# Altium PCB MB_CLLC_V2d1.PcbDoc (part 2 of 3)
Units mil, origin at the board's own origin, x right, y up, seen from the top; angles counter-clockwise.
Board outline 9000 x 7000 mil, 2 copper layers (Top Layer, Bottom Layer); 436 components, 223 nets, 1335 pads, 200 vias.
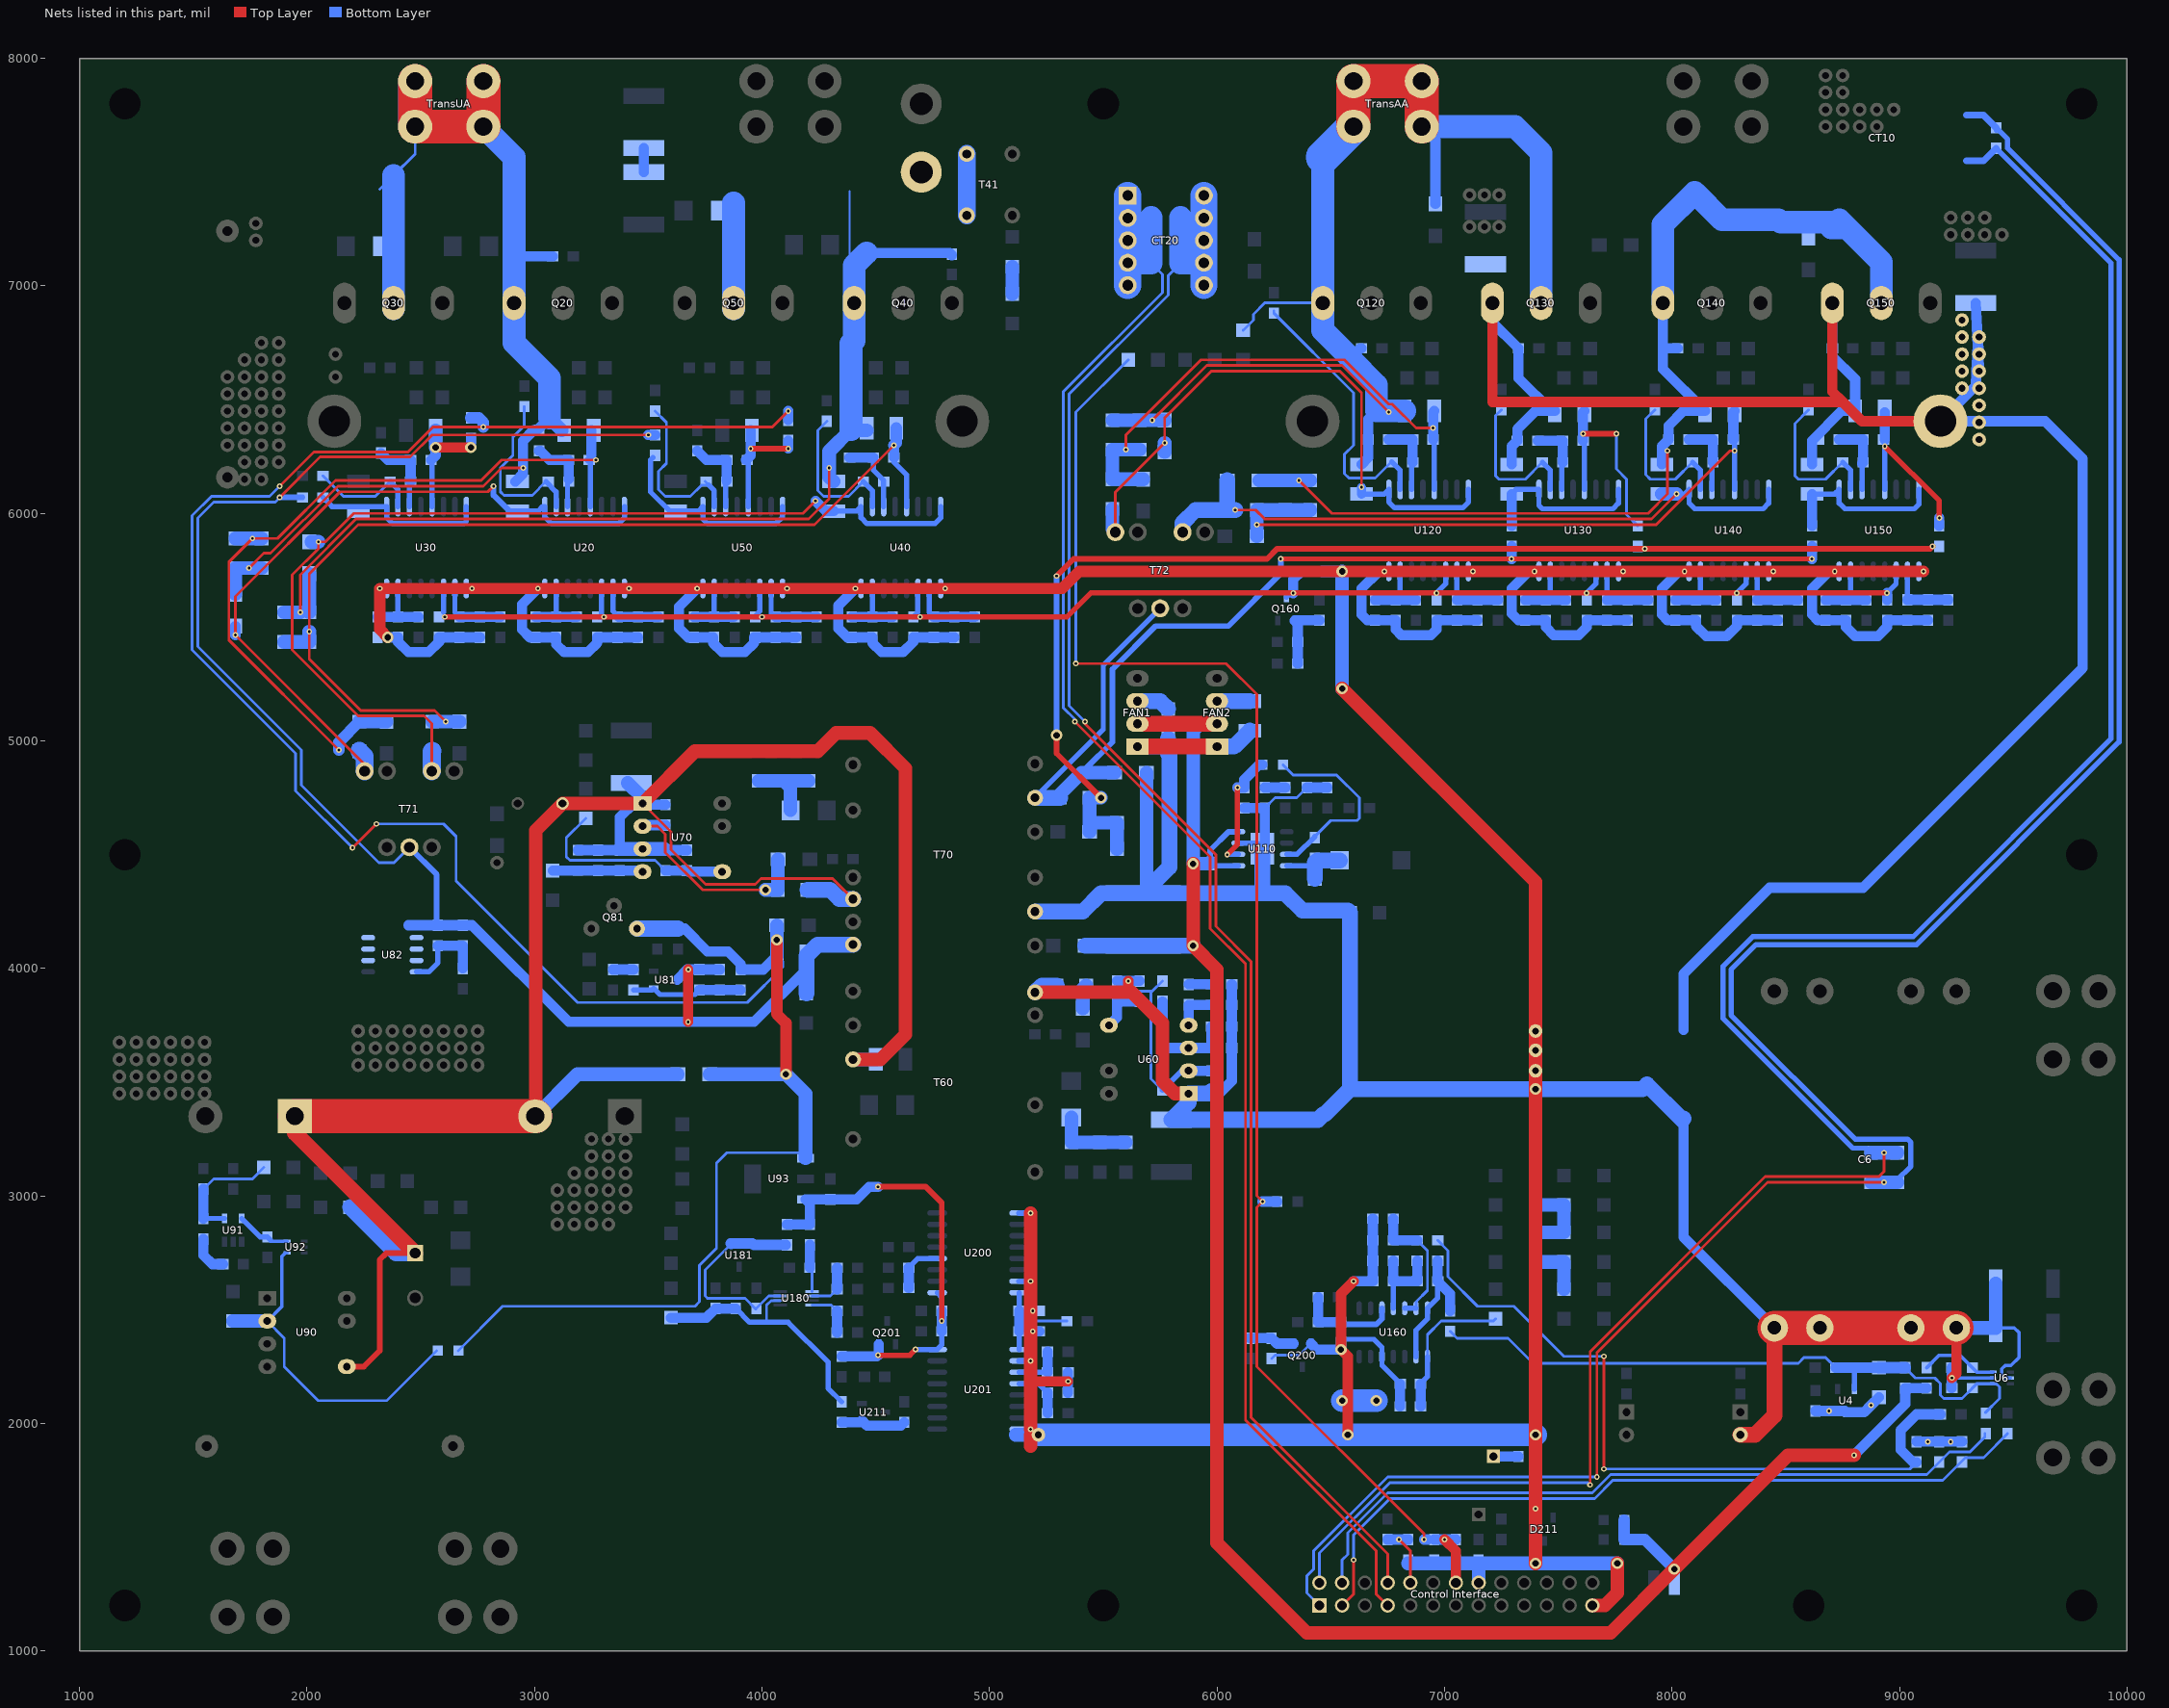
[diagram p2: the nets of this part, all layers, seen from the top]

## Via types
v1: diameter 25, hole 12, Top Layer to Bottom Layer, 169 vias
v2: diameter 50, hole 28, Top Layer to Bottom Layer, 31 vias

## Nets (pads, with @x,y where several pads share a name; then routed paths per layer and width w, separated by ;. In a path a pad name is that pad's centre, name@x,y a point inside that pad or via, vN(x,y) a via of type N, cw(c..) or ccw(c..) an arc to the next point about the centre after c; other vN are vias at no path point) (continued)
+3.3VBU: C93.2 C203.2 C206.2 Q201.2 R189.2 R190.1 R211.1 U93.3 U200.1 U201.16 | length 2135.8
  Top Layer w23: v1(4510,2300) 4650,2300 v1(4675,2325)
  Top Layer w25: v1(4510,3040) 4720,3040 4790,2970 v1(4790,2450)
  Bottom Layer w23: v1(4675,2325) U201.16@4770,2325 4790,2345 C206.2@4790,2405 ; U200.1@4770,2575 4790,2555 C203.2@4790,2495
  Bottom Layer w45: R190.1@4110,2875 R189.2@4210,2875 4210,2965.59 U93.3@4191.14,2984.45 4244.45,2984.45 4245,2985 C93.2@4300,2985 4415,2985 4470,3040 v1(4510,3040) ; R211.1@4350,2295 4505,2295 v1(4510,2300) 4512.6,2302.6 Q201.2@4512.6,2347.64 ; C206.2@4790,2405 v1(4790,2450) C203.2@4790,2495
+6V: C5.2 C8.2 R4.2 R5.1 R160.1 R240.1 U4.2 U6.1 | length 2859
  Bottom Layer w12: R160.1@7025,2405 7055,2375 7280,2375 7390,2265 8555,2265 8580,2290 8675,2290 R5.1@8720,2245 ; R4.2@9025,2245 9070,2200 9155,2200 9180,2175 9180,2125 9195,2110 9275,2110 C8.2@9320,2155 ; R240.1@9377.5,2047.5 9440,2110 9440,2160 9426,2174 U6.1@9412.5,2174
  Bottom Layer w15: C8.2@9320,2155 9339,2174 U6.1@9412.5,2174
  Bottom Layer w23: U4.2@8802.4,2151.18 8802.4,2227.4 8820,2245
  Bottom Layer w45: R5.1@8720,2245 8820,2245 C5.2@8910,2245
  Bottom Layer w50: C5.2@8910,2245 R4.2@9025,2245
+12V: C76.1 C110.2 D75.2 D191.2 D192.2 FAN1.2 FAN2.2 L190.2 R4.1 R232.1 U110.1 U110.4 | length 9115.2
  Top Layer w60: v2(5895,4460) v2(5895,4100) 6000,3995 6000,1475 6395,1080 7730,1080 v2(8010,1360) 8510,1860 v1(8800,1860)
  Top Layer w70: FAN1.2@5650,5075 FAN2.2@6000,5075
  Bottom Layer w25: C110.2@5963,4460 5954,4451 U110.1@6093.7,4451 ; C110.2@5970,4467 5970,4520 6051,4601 U110.4@6093.7,4601
  Bottom Layer w45: v1(8800,1860) 9025,2085 R4.1@9025,2155 R232.1@9120,2155
  Bottom Layer w50: D191.2@7790,1575 D192.2@7790,1490 7880,1490 v2(8010,1360)
  Bottom Layer w60: C110.2@5970,4467 5963,4460 v2(5895,4460) 5895,5045 5925,5075 FAN2.2@6000,5075
  Bottom Layer w70: D75.2@5420,4100 C76.1@5675,4100 ; C76.1@5685,4100 v2(5895,4100)
+15V_BA: C77.2 D76.2 R76.2 R77.2 R137.1 R157.1 | length 5389.6
  Top Layer w25: v2(5295,5025) 5295,4945 v2(5490,4750) ; v1(5295,5725) 5370,5800 6220,5800 6265,5845 v1(7880,5845) 9135,5845 v1(9145,5855)
  Bottom Layer w25: v2(5295,5025) v1(5295,5725)
  Bottom Layer w60: D76.2@5440,4600 5440,4640 ; v2(5490,4750) C77.2@5440,4750 5440,4640 ; R77.2@5555,4640 5440,4640 ; R76.2@5560,4525 R77.2@5560,4640
+15V_BA_A: C80.2 C120.1 C122.1 D80.2 R80.2 R81.2 U120.5 | length 2410.1
  Top Layer w12: v1(5600,6280) 5600,6345 5930,6675 6560,6675 6755,6480 6770,6480 6875,6375 v1(6950,6375)
  Bottom Layer w23: C122.1@6950,6325 6955,6320 U120.5@6955,6105
  Bottom Layer w45: C122.1@6950,6325 v1(6950,6375) 6950,6445 C120.1@6955,6450
  Bottom Layer w60: R81.2@5660,6280 v1(5600,6280) R80.2@5540,6280 C80.2@5540,6150 D80.2@5675,6150
+15V_BA_B: C79.2 C140.1 C142.1 D78.2 R78.2 R79.2 U140.5 | length 2933.8
  Top Layer w12: v1(6175,5950) 7930,5950 8255,6275 v1(8275,6275)
  Bottom Layer w23: C142.1@8270,6325 8275,6320 v1(8275,6275) U140.5@8275,6105
  Bottom Layer w45: C142.1@8270,6325 8270,6445 C140.1@8275,6450
  Bottom Layer w60: D78.2@6175,5900 v1(6175,5950) C79.2@6175,6015 R79.2@6300,6015 R78.2@6410,6015
+20V: C86.2 D71.1 D86.2 D91.1 Q81.1 R37.1 R57.1 R82.2 R83.2 R86.1 U93.1 | length 11604.2
  Top Layer w12: v1(1880,6120) 2030,6270 2443.89,6270 2553.89,6380 v1(2775,6380) 4045,6380 v1(4115,6450) ; v1(2200,4530) v1(2305,4635)
  Top Layer w50: v2(4065,4125) 4065,3800 4105,3760 v2(4105,3535)
  Bottom Layer w12: v1(1880,6120) 1835,6075 1580,6075 1495,5990 1495,5400 1950,4945 1950,4780 v1(2200,4530) ; v1(2305,4635) 2600,4635 2655,4580 2655,4385 3190,3850 3935,3850 4090.11,4005.11 4090.11,4029.89 C86.2@4065,4055 ; D91.1@2665,2320 2860,2515 3705,2515 3725,2535 3725,2695 3800,2770 3800,3145 3845,3190 4166.69,3190 U93.1@4191.14,3165.55
  Bottom Layer w45: R83.2@3630,4175 3660,4175 3760,4075 3850,4075 3905,4020 R86.1@3905,3995 4005,3995 C86.2@4065,4055 ; R57.1@4115,6410 v1(4115,6450)
  Bottom Layer w50: R37.1@2720,6420 2755,6420 2775,6400 v1(2775,6380)
  Bottom Layer w60: D71.1@3770,3535 v2(4105,3535) 4191.14,3448.86 U93.1@4191.14,3165.55 ; C86.2@4065,4055 v2(4065,4125) D86.2@4065,4190
  Bottom Layer w70: Q81.1@3450,4175 R82.2@3540,4175 R83.2@3630,4175
+20V_BU_A: C20.1 C22.1 C102.2 D102.2 R102.2 R103.2 U20.5 | length 3547.5
  Top Layer w12: v1(2140,4960) 1656.5,5443.5 1656.5,5786.5 v1(1760,5890) 1870,5890 2125,6145 2765,6145 2855,6235 v1(3270,6235)
  Bottom Layer w23: C22.1@3230,6235 C22.1@3235,6230 ; C22.1@3240,6235 3245,6230 U20.5@3245,6030
  Bottom Layer w45: C22.1@3250,6255 C20.1@3250,6365
  Bottom Layer w50: v1(2140,4960) 2140,4995 C102.2@2230,5085
  Bottom Layer w60: R102.2@1685,5890 v1(1760,5890) R103.2@1800,5890 ; C102.2@2230,5085 D102.2@2350,5085
+20V_BU_B: C40.1 C42.1 C100.2 D100.2 R100.2 R101.2 U40.5 | length 4519.9
  Top Layer w12: v1(2610,5085) 2561,5134 2236,5134 2010,5360 v1(2010,5480) 2010,5735 2225,5950 4230,5950 v1(4580,6300)
  Bottom Layer w23: C42.1@4580,6225 4635,6170 U40.5@4635,6030
  Bottom Layer w45: C42.1@4580,6245 v1(4580,6300)
  Bottom Layer w50: v1(4580,6300) 4590,6310 C40.1@4590,6375
  Bottom Layer w60: R101.2@1900,5435 R100.2@2010,5435 v1(2010,5480) ; C100.2@2550,5085 v1(2610,5085) D100.2@2670,5085
-5V_BA: C77.1 D77.1 R138.2 R158.2 T70.13 T72.3 | length 5386.3
  Top Layer w23: v1(6280,5800) v1(7295,5800) v1(8615,5800)
  Bottom Layer w23: T70.13@5200,4750 5500,5050 5500,5332.48 T72.3@5750,5582.48
  Bottom Layer w25: 5425,4865 5425,4880 5540,4995 5540,5315 5730,5505 6050,5505 6280,5735 v1(6280,5800)
  Bottom Layer w45: v1(7295,5800) R138.2@7295,5855 ; v1(8615,5800) R158.2@8615,5855
  Bottom Layer w60: C77.1@5310,4750 5310,4765 5405,4860 D77.1@5550,4860
  Bottom Layer w70: T70.13@5200,4750 C77.1@5310,4750
-5V_BA_A: C80.1 C123.1 D81.1 T72.10 U120.1 U120.8 | length 2783.5
  Top Layer w12: T72.10@5553.15,5917.52 5553.15,6093.15 v1(5770,6310) 5770,6420 5975,6625 6540,6625 6635,6530 v1(6635,6115)
  Bottom Layer w23: C123.1@6635,6085 6735,6085 U120.1@6755,6105 6755,6050 6780,6025 7080,6025 7105,6050 U120.8@7105,6105
  Bottom Layer w40: C123.1@6635,6085 v1(6635,6115)
  Bottom Layer w60: C80.1@5540,6020 5540,5930.67 T72.10@5553.15,5917.52 ; D81.1@5770,6270 v1(5770,6310)
-5V_BA_B: C79.1 C143.1 D79.1 T72.7 U140.1 U140.8 | length 3047
  Top Layer w12: v1(6080,6015) 6170,6015 6210,5975 7910,5975 v1(8020,6085)
  Bottom Layer w23: v1(8020,6085) 8055,6085 U140.1@8075,6105 8075,6045 8100,6020 8400,6020 8425,6045 U140.8@8425,6105
  Bottom Layer w60: C143.1@7955,6085 v1(8020,6085)
  Bottom Layer w70: T72.7@5848.43,5917.52 5848.43,5958.43 5905,6015 C79.1@6045,6015 ; D79.1@6045,6145 C79.1@6045,6015 ; v1(6080,6015) C79.1@6045,6015
-5V_BU_A: C23.1 C102.1 D103.1 T71.10 U20.1 U20.8 | length 3235.8
  Top Layer w12: T71.10@2253.15,4867.52 2253.15,4896.85 v1(1685,5465) 1685,5635 2145,6095 2795,6095 v1(2820,6120)
  Bottom Layer w23: C23.1@2915,6010 C23.1@2925,6010 3015,6010 U20.1@3035,6030 ; U20.1@3045,6030 3045,5985 3075,5955 3370,5955 3395,5980 U20.8@3395,6030
  Bottom Layer w25: v1(2820,6120) 2820,6080 2890,6010 C23.1@2915,6010
  Bottom Layer w45: v1(1685,5465) D103.1@1685,5505
  Bottom Layer w80: C102.1@2230,4955 2253.15,4931.85 T71.10@2253.15,4867.52
-5V_BU_B: C43.1 C100.1 D101.1 T71.7 U40.1 U40.8 | length 4567.6
  Top Layer w12: T71.7@2548.43,4867.52 2548.43,5076.57 2515,5110 2225,5110 1935,5400 1935,5730 2050,5845 v1(2050,5875) 2080,5875 2205,6000 4180,6000 v1(4235,6055)
  Bottom Layer w0: D101.1@2010,5875 2015,5880 D101.1@2020,5875
  Bottom Layer w23: C43.1@4315,6010 4415,6010 U40.1@4435,6030 4435,5981.69 4461.69,5955 4760,5955 4785,5980 U40.8@4785,6030
  Bottom Layer w45: v1(4235,6055) 4280,6010 C43.1@4315,6010
  Bottom Layer w60: D101.1@2020,5875 v1(2050,5875)
  Bottom Layer w80: T71.7@2548.43,4867.52 2548.43,4953.43 C100.1@2550,4955
-5VBU: C86.1 C87.1 C88.1 R38.2 R58.2 R68.2 R87.2 R89.2 T70.8 T71.3 U81.3 U82.2 | length 7510.3
  Top Layer w12: v1(1880,6070) 2058,6248 2453,6248 2550,6345 v1(3500,6345)
  Top Layer w45: v1(3675,3765) 3675.59,3765.59 v1(3675.59,3995)
  Bottom Layer w12: v1(1880,6070) 1860,6050 1590,6050 1520,5980 1520,5415 1975,4960 1975,4805 2315,4465 2382.52,4465 T71.3@2450,4532.48
  Bottom Layer w25: v1(1880,6070) R38.2@1980,6070 ; T71.3@2450,4532.48 2570,4412.48 C88.1@2570,4190
  Bottom Layer w45: 2445,4190 2570,4190 C88.1@2575,4190 R89.2@2685,4190 2725,4190 3150,3765 v1(3675,3765) 3965,3765 4195,3995 ; v1(3500,6345) R58.2@3530,6345 ; U81.3@3626.18,3950 3671.18,3995 v1(3675.59,3995) R87.2@3725,3995 R68.2@3815,3995
  Bottom Layer w70: C87.1@4195,3890 4195,3995 C86.1@4195,4055 4245,4105 T70.8@4400,4105
C_BA_A: C120.2 C123.2 D81.2 D130.2 Q120.3 Q130.2 R12.2 R80.1 R81.1 R123.1 R124.1 TransAA.1 | length 6023.5
  Top Layer w12: v1(5715,6410) 5955,6650 6550,6650 v1(6755,6445)
  Top Layer w150: TransAA.1@6600,7700 TransAA.1@6600,7900 TransAA.1@6900,7900 TransAA.1@6900,7700
  Bottom Layer w12: R12.2@6115,6805 6160,6850 6160,6875 6210,6925 Q120.3@6465,6925
  Bottom Layer w45: 6585,6680 6587.5,6682.5 6630,6725 R123.1@6635,6725 ; C123.2@6635,6215 6665,6245 R124.1@6665,6325 6665,6415 6700,6450 ; TransAA.1@6900,7700 6960,7640 D130.2@6960,7360
  Bottom Layer w60: R80.1@5540,6410 R81.1@5660,6410 v1(5715,6410) D81.2@5770,6410
  Bottom Layer w100: 6465,7565 Q120.3@6465,6925 6465,6805 6587.5,6682.5 ; 6585,6680 6700,6565 6700,6450 C120.2@6825,6450 ; TransAA.1@6900,7700 7310,7700 7425,7585 Q130.2@7425,6925
  Bottom Layer w150: 6465,7565 TransAA.1@6600,7700
C_BA_B: C140.2 C143.2 CT10.6 CT10.12 D79.2 D150.2 Q140.3 Q150.2 R78.1 R79.1 R143.1 R144.1 | length 4914.6
  Top Layer w12: v1(6360,6145) 6505,6000 7895,6000 7980,6085 v1(7980,6275)
  Bottom Layer w45: C143.2@7955,6215 7955,6295 R144.1@7985,6325 7985,6385 8050,6450 C140.2@8145,6450 7960,6635 7960,6725 ; Q140.3@7960,6925 7960,6725 ; R143.1@8025,6725 7960,6725
  Bottom Layer w60: D79.2@6185,6145 R79.1@6300,6145 v1(6360,6145) R78.1@6410,6145
  Bottom Layer w100: Q140.3@7960,6925 7960,7270 8100,7410 8220,7290 8467.65,7290 8477.65,7280 8725,7280 ; Q150.2@8920,6925 8920,7105 8735,7290 8725,7280 ; 8725,7280 8700,7255 8750,7255 8725,7280
C_BU_A: C20.2 C23.2 D30.2 D103.2 Q20.3 Q30.2 R23.1 R24.1 R102.1 R103.1 TransUA.1 | length 5440.3
  Top Layer w12: v1(1745,5760) 1810,5825 1840,5825 2135,6120 2775,6120 2855,6200 v1(2950,6200)
  Top Layer w150: TransUA.1@2475,7900 TransUA.1@2475,7700 TransUA.1@2775,7700 TransUA.1@2775,7900
  Bottom Layer w12: 2320,7425 2380,7485 2475,7580 TransUA.1@2475,7700
  Bottom Layer w45: 2910,7130 R23.1@3080,7130 ; C23.2@2915,6140 2950,6175 v1(2950,6200) 2950,6320 2995,6365 3010,6365 3065,6420
  Bottom Layer w60: D103.2@1685,5645 R102.1@1685,5760 v1(1745,5760) R103.1@1800,5760 ; 3065,6420 C20.2@3120,6365
  Bottom Layer w100: Q30.2@2380,6900 Q30.2@2380,6925 2380,7485 ; TransUA.1@2775,7700 2910,7565 2910,7130 Q20.3@2910,6925 2910,6750 3065,6595 3065,6420
  Bottom Layer w150: TransUA.1@2475,7700 TransUA.1@2475,7900
C_BU_B: C40.2 C43.2 D50.2 D101.2 pad.61 Q40.3 Q50.2 R43.1 R44.1 R100.1 R101.1 T41.2 | length 5785.2
  Top Layer w12: v1(1970,5565) 1970,5730 2215,5975 4205,5975 4295,6065 v1(4295,6200)
  Bottom Layer w10: Q40.3@4385,6900 4385,7415
  Bottom Layer w45: 4460,7145 4825,7145 R43.1@4835,7135
  Bottom Layer w60: R101.1@1900,5565 v1(1970,5565) ; R100.1@2010,5565 D101.2@2010,5735 ; C43.2@4315,6140 4295,6160 v1(4295,6200) R44.1@4295,6245 4295,6273 4391,6369 4395,6365 C40.2@4460,6365
  Bottom Layer w80: T41.2@4900,7310 T41.2@4900,7580
  Bottom Layer w100: Q50.2@3875,6900 Q50.2@3875,6925 3875,7365 ; 4391,6369 4391,6746 4405,6760 Q40.3@4405,6925 4405,7090 4460,7145
GND: "Control Interface.16" "Control Interface.25" C5.1 C6.2 C7.1 C8.1 C24.1 C25.1 C26.2 C27.1 C34.1 C35.1 C36.2 C37.1 C44.1 C45.1 C46.2 C47.1 C54.1 C55.1 C56.2 C57.1 C61.1 C62.1 C63.1 C64.1 C66.1 C68.1 C76.2 C110.1 C111.1 C112.1 C114.1 C115.1 C116.1 C124.1 C125.1 C126.2 C127.1 C128.1 C130.2 C133.2 C134.1 C135.1 C136.2 C137.1 C144.1 C145.1 C146.2 C147.1 C148.1 C150.2 C153.2 C154.1 C155.1 C156.2 C157.1 C161.1 C162.1 C164.1 C169.1 C170.1 C194.1 C201.1 C202.1 C204.1 C208.1 C209.1 C212.1 C217.1 C239.1 C240.1 D77.2 D111.1 D211.1 FAN1.1 FAN2.1 HS2.1 pad.8@5215,1950 pad.50 pad.51 pad.52 pad.53 pad.54 pad.55 pad.56@8450,2420 pad.56@9250,2420 pad.57 pad.58 pad.59 Power.2 Q130.3 Q150.3 Q200.2 R6.2 R27.2 R39.2 R47.2 R59.2 R62.2 R64.2 R66.2 R76.1 R77.1 R111.2 R112.2 R127.2 R133.1 R134.1 R139.2 R147.2 R153.1 R154.1 R159.2 R162.2 R164.2 R167.2 R168.2 R194.2 R217.2 R230.2 R231.2 T60.8 T70.10 U4.3 U6.2 U6.5 U20.9 U20.16 U30.9 U30.16 U40.9 U40.16 U50.9 U50.16 U60.1 U110.3 U110.9 U120.9 U120.16 U130.9 U130.16 U140.9 U140.16 U150.9 U150.16 U160.12 U200.9 U200.15 U201.2 U201.8 | length 48783.6
  Top Layer w45: 5180,2185 v1(5345,2185) ; v1(5610,3945) 5610,3910 5625,3895 ; v2(6575,1950) 6575,2295 v2(6545,2325) 6545,2570 v1(6600,2625) ; Q130.3@7210,6925 7210,6490 8750,6490 ; Q150.3@8705,6925 8705,6535 8750,6490 ; HS2.1@9180,6405 8835,6405 8750,6490 ; v1(9230,2200) 9250,2220 pad.56@9250,2420
  Top Layer w50: v2(2355,5455) 2320,5490 v1(2320,5670) v1(2725,5670) v1(3015,5670) v1(3415,5670) v1(3715,5670) v1(4110,5670) v1(4410,5670) v1(4805,5670) 5320,5670 5395,5745 v2(6550,5745) v1(6735,5745) v1(7125,5745) v1(7395,5745) v1(7785,5745) v1(8055,5745) v1(8445,5745) v1(8715,5745) v1(9105,5745)
  Top Layer w60: 5180,1900 5180,1950 ; v1(5180,1975) 5180,2185 v1(5180,2275) v1(5180,2625) v1(5180,2925) ; T60.8@5200,3895 5625,3895 5760,3760 5760,3505 5815,3450 U60.1@5875,3450 ; v2(6550,5230) 7400,4380 pad.59@7400,3725 pad.58@7400,3640 pad.57@7400,3550 v2(7400,3470) v2(7400,1950) v1(7400,1625) v2(7400,1385) ; 7650,1200 7705,1200 7760,1255 v2(7760,1385)
  Top Layer w70: FAN1.1@5650,4975 FAN2.1@6000,4975 ; Power.2@8300,1950 8365,1950 8450,2035 pad.56@8450,2420
  Top Layer w150: pad.56@8450,2420 C6.2@8650,2420 C6.2@9050,2420 pad.56@9250,2420
  Bottom Layer w12: C112.1@6210,4705 6255,4750 6350,4750 R112.2@6395,4795 ; C204.1@6240,2285 6255,2300 6361.22,2300 Q200.2@6412.4,2351.18
  Bottom Layer w15: v1(9230,2200) U6.2@9412.5,2200 ; R231.2@9423.03,2420 9505,2420 9525,2400 9525,2290 9490,2255 9465,2255 9450,2240 9450,2210 9460,2200 U6.5@9487.5,2200
  Bottom Layer w23: v1(2320,5670) U30.16@2350,5670 ; U30.9@2700,5670 v1(2725,5670) ; v1(4410,5670) U40.16@4435,5670 ; U110.3@6093.7,4551 6175,4551 U110.9@6200,4526 ; C170.1@6545,2355 6560,2370 6690,2370 6725,2335 U160.12@6725,2293.7 6725,2255 C169.1@6805,2175
  Bottom Layer w25: U201.2@5130,2275 v1(5180,2275) ; U200.15@5130,2625 v1(5180,2625) ; U200.9@5130,2925 v1(5180,2925) ; v1(7400,1625) 7402.6,1622.4 D211.1@7402.6,1586.18
  Bottom Layer w45: v2(2355,5455) C34.1@2400,5455 2400,5435 2445,5390 2535,5390 2580,5435 C36.2@2580,5455 C37.1@2670,5455 R39.2@2760,5455 ; v1(3015,5670) 2945,5600 2945,5490 2980,5455 C25.1@3005,5455 C24.1@3095,5455 3095,5425 3130,5390 3235,5390 3275,5430 C26.2@3275,5455 ; C26.2@3285,5455 C27.1@3365,5455 R27.2@3455,5455 ; v1(3715,5670) 3635,5590 3635,5495 3675,5455 C55.1@3700,5455 3785,5455 3785,5430 3825,5390 3925,5390 3965,5430 3965,5455 C56.2@3970,5455 C57.1@4060,5455 R59.2@4150,5455 ; v1(4410,5670) 4335,5595 4335,5495 4375,5455 C45.1@4395,5455 C44.1@4485,5455 4485,5430 4525,5390 4620,5390 4665,5435 C46.2@4665,5455 C47.1@4755,5455 R47.2@4845,5455 ; v1(5190,2405) C212.1@5220,2405 ; C202.1@5345,2135 v1(5345,2185) C208.1@5345,2225 ; C62.1@5560,3945 v1(5610,3945) R62.2@5660,3945 ; C61.1@5975,3460 6020,3460 6065,3505 C66.1@6065,3650 R66.2@6065,3745 C64.1@6065,3840 R64.2@6065,3930 ; C111.1@6120,4705 C112.1@6210,4705 6210,4536 U110.9@6200,4526 ; R112.2@6395,4795 R111.2@6485,4795 ; Q200.2@6412.4,2351.18 6438.58,2325 v2(6545,2325) ; v1(6600,2625) C161.1@6685,2625 R162.2@6685,2715 C162.1@6685,2805 R164.2@6685,2900 ; v1(6735,5745) 6710,5745 6635,5670 6635,5555 6660,5530 C125.1@6695,5530 C124.1@6785,5530 6785,5490 6810,5465 6940,5465 6965,5490 C126.2@6965,5530 C127.1@7055,5530 R127.2@7145,5530 ; R168.2@6805,2075 C169.1@6805,2175 ; Q130.3@7210,6925 7210,6840 R133.1@7325,6725 7325,6595 C130.2@7470,6450 ; C133.2@7295,6215 7295,6295 R134.1@7320,6320 7320,6370 7400,6450 C130.2@7470,6450 ; v1(7395,5745) 7370,5745 7295,5670 7295,5560 7325,5530 C135.1@7355,5530 C134.1@7445,5530 7445,5500 7480,5465 7590,5465 7625,5500 C136.2@7625,5530 C137.1@7715,5530 R139.2@7805,5530 ; C130.2@7485,6450 C130.2@7470,6450 ; 8050,3340 8050,2820 pad.56@8450,2420 ; 8050,3730 8050,3975 8430,4355 8840,4355 9805,5320 9805,6240 9640,6405 HS2.1@9180,6405 9335,6560 9338.14,6620.61 9338.39,6625.6 9341.67,6688.88 9342.26,6700.4 9344.28,6739.41 ; v1(8055,5745) 8030,5745 7955,5670 7955,5555 7980,5530 C145.1@8015,5530 C144.1@8105,5530 8105,5505 8150,5460 8240,5460 8285,5505 C146.2@8285,5530 C147.1@8375,5530 R147.2@8465,5530 ; C153.2@8615,6215 8615,6320 8745,6450 C150.2@8805,6450 8805,6590 8705,6690 R153.1@8705,6725 Q150.3@8705,6925 ; R6.2@8630,2055 v1(8690,2055) 8758.82,2055 U4.3@8765,2048.82 8843.82,2048.82 v1(8875,2080) C5.1@8910,2115 ; C6.2@8649.72,2412.52 C6.2@8650.09,2412.5 ; v1(8715,5745) 8690,5745 8615,5670 8615,5555 8640,5530 C155.1@8675,5530 C154.1@8765,5530 8765,5500 8805,5460 8905,5460 8945,5500 C156.2@8945,5530 C157.1@9035,5530 R159.2@9125,5530 ; C164.1@9075,1920 v1(9125,1920) C240.1@9175,1920 v1(9225,1920) C239.1@9275,1920 ; C8.1@9230,2155 v1(9230,2200) C7.1@9230,2245 ; C148.1@9335,6925 9342.52,6774.63 9344.28,6739.41 ; 9344.28,6739.41 9345.55,6763.94 9346.13,6775.2 9346.14,6774.9 9348.07,6699.95 pad.51@9350,6625 9346.26,6699.81 9344.28,6739.41
  Bottom Layer w50: R167.2@6460,5745 v2(6550,5745)
  Bottom Layer w60: 5115,1950 pad.8@5215,1950 ; C76.2@5690,4345 R76.1@5690,4525 R77.1@5690,4640 D77.2@5690,4860 ; v2(6550,5230) v2(6550,5745) ; C209.1@6840,1385 v2(7400,1385) v2(7760,1385) ; 7150,1300 R217.2@7150,1375 ; pad.56@9250,2420 R231.2@9423.03,2420 R230.2@9423.03,2615
  Bottom Layer w70: T60.8@5200,3895 5230,3925 C63.1@5295,3925 ; T70.10@5200,4250 5410,4250 5490,4330 C76.2@5675,4330 ; FAN1.1@5650,4975 5755,4975 ; C115.1@5785,5010 5785,4945 5790,4940 5790,4445 5690,4345 C76.2@5675,4330 ; C61.1@5975,3460 5965,3450 U60.1@5875,3450 5875,3410 C68.1@5800,3335 6443.93,3335 6468.93,3360 6475,3360 6585,3470 ; FAN2.1@6000,4975 6075,4975 C116.1@6145,5045 ; U110.9@6200,4526 6200,4330 ; 8050,3340 8045,3335 7890,3490 7870,3470 v2(7400,3470) 6585,3470 ; C76.2@5675,4330 C110.1@5970,4330 6200,4330 ; 6200,4330 6300,4330 6375,4255 D111.1@6430,4255 6575,4255 C114.1@6585,4245 6585,3470
  Bottom Layer w100: pad.8@5215,1950 v2(6575,1950) v2(7400,1950) ; v2(6550,2100) v2(6700,2100)
  other v1: 5190,2495
Half-BUS: C2.2 C3.1 C67.1 C70.1 C72.1 C73.1 C74.1 C98.1 C99.1 D70.1 D71.2 L90.1 R70.2 R72.2 R94.2 T60.11 T70.6 U70.1 U70.3 U90.5 | length 10711.8
  Top Layer w12: U70.1@3475,4725 3600,4600 3600,4522 3752,4370 3970,4370 3995,4395 4310,4395 T70.6@4400,4305
  Top Layer w25: U90.5@2175,2250 2250,2250 2320,2320 2320,2720 2348.43,2748.43 L90.1@2475,2748.43
  Top Layer w50: C2.2@3003.15,3350 C2.2@3005,3351.85
  Top Layer w60: C2.2@3005,3351.85 3005,4606.57 C98.1@3123.43,4725 U70.1@3475,4725 3705,4955 4245,4955 4325,5035 4475,5035 4630,4880 4630,3710 4520,3600 T60.11@4400,3600
  Top Layer w70: C3.1@1946.85,3350 1946.85,3276.57 L90.1@2475,2748.43
  Top Layer w150: C3.1@1946.85,3350 C2.2@3003.15,3350
  Bottom Layer w45: D70.1@3190,4520 R70.2@3280,4520 C72.1@3375,4520 C72.1@3380,4520 ; C72.1@3375,4525 3375,4665 3435,4725 U70.1@3475,4725 3480,4720 C70.1@3575,4720 ; R72.2@3570,4525 R72.2@3575,4520 C73.1@3670,4520
  Bottom Layer w60: C2.2@3003.15,3350 3188.15,3535 D71.2@3630,3535 ; C72.1@3375,4525 U70.3@3475,4525 R72.2@3570,4525 ; C99.1@3410,4815 3475,4750 U70.1@3475,4725 ; T60.11@4400,3600 C67.1@4500,3600
  Bottom Layer w70: R94.2@2190,2950 2391.57,2748.43 L90.1@2475,2748.43 ; C74.1@4200,4345 4300,4345 4340,4305 T70.6@4400,4305
NetC7_2: C7.2 R232.2 U6.3 | length 345.9
  Bottom Layer w15: R232.2@9120,2245 9175,2300 9265,2300 C7.2@9320,2245 9339,2226 U6.3@9412.5,2226
NetC11_1: "Control Interface.2" C11.1 CT10.4 R10.1 R11.1 | length 10056.4
  Top Layer w12: v1(7640,1730) 7640,2315 8410,3085 8910,3085 8932.5,3107.5 v1(8932.5,3190)
  Bottom Layer w12: 6450,1300 6450,1430 6760,1740 7630,1740 v1(7640,1730)
  Bottom Layer w23: R10.1@8875,3190 8855,3210 8795,3210 8225,3780 8225,4010 8355,4140 9060,4140 9930,5010 9930,7100 C11.1@9425,7605
  Bottom Layer w30: CT10.4@9295,7550 9370,7550 C11.1@9425,7605
  Bottom Layer w60: R10.1@8875,3190 v1(8932.5,3190) R11.1@8990,3190
NetC11_2: "Control Interface.1" C11.2 CT10.2 R10.2 R11.2 | length 10530.6
  Top Layer w12: v1(7670,1765) 7670,2310.3 8419.69,3060 v1(8932.5,3060)
  Bottom Layer w12: 6450,1200 6395,1255 6395,1330 6425,1360 6425,1440 6750,1765 v1(7670,1765)
  Bottom Layer w23: R10.2@8875,3060 R10.2@8875,3075 ; R11.2@8990,3060 8990,3070 9050,3130 9050,3235 9035,3250 8805,3250 8260,3795 8260,3995 8370,4105 9075,4105 9965,4995 9965,7115 9475,7605 9475,7645 C11.2@9425,7695 C11.2@9425,7685
  Bottom Layer w30: CT10.2@9295,7750 9370,7750 C11.2@9425,7695
  Bottom Layer w60: R10.2@8875,3060 v1(8932.5,3060) R11.2@8990,3060
NetC12_1: "Control Interface.8" C12.1 CT20.2 R15.1 R16.1 | length 7279.1
  Top Layer w12: v1(5420,5085) 5420,5075 5995,4500 5995,4185 6150,4030 6150,2026.11 6750,1426.11 6750,1300
  Bottom Layer w12: v1(5420,5085) 5350,5155 5350,6525 5785,6960 5785,7045 R16.1@5840,7100
  Bottom Layer w100: R15.1@5840,7300 R16.1@5840,7100 5942.52,7100 CT20.2@5942.52,7101.57
  Bottom Layer w120: CT20.2@5942.52,7003.15 CT20.2@5942.52,7100 ; CT20.2@5942.52,7101.57 CT20.2@5942.52,7200 CT20.2@5942.52,7298.43 CT20.2@5942.52,7396.85
NetC12_2: "Control Interface.7" C12.2 CT20.1 R15.2 R16.2 | length 7388
  Top Layer w12: v1(5375,5085) 5970,4490 5970,4175 6125,4020 6125,2015 6700,1440 6700,1250 6750,1200
  Bottom Layer w12: v1(5375,5085) 5375,5095 5325,5145 5325,6535 5760,6970 5760,7050 R16.2@5710,7100
  Bottom Layer w100: CT20.1@5607.48,7101.57 5609.06,7100 R16.2@5710,7100 R15.2@5710,7300
  Bottom Layer w120: CT20.1@5607.48,7003.15 CT20.1@5607.48,7101.57 CT20.1@5607.48,7200 CT20.1@5607.48,7298.43 CT20.1@5607.48,7396.85
NetC21_1: C21.1 C22.2 R24.2 U20.3 | length 353.6
  Bottom Layer w23: U20.3@3145,6030 3145,6145 C21.1@3150,6150
  Bottom Layer w45: R24.2@3020,6275 3025,6275 3065,6235 C22.2@3150,6235 C21.1@3150,6150
NetC21_2: C21.2 R20.2 U20.2 | length 778.2
  Bottom Layer w12: R20.2@2955,6470 2955,6385 2905,6335 2905,6255 2850,6200 2850,6095 2865,6080 2990,6080 C21.2@3050,6140
  Bottom Layer w23: C21.2@3050,6140 3095,6095 U20.2@3095,6030
NetC24_2: C24.2 C25.2 R25.2 U20.15 | length 309.1
  Bottom Layer w23: C24.2@3085,5545 3095,5555 U20.15@3095,5670
  Bottom Layer w45: C25.2@3005,5545 3085,5545 C24.2@3095,5545 R25.2@3185,5545
NetC26_1: C26.1 C36.1 C46.1 C56.1 C126.1 C136.1 C146.1 C156.1 Q160.3 R167.1 U20.11 U30.11 U40.11 U50.11 U120.11 U130.11 U140.11 U150.11 | length 7594.8
  Top Layer w23: v1(2605,5545) v1(3305,5545) v1(4000,5545) v1(4695,5545) 5340,5545 5445,5650 v1(6335,5650) v1(6965,5650) v1(7625,5650) v1(8285,5650) v1(8945,5650)
  Bottom Layer w23: C36.1@2600,5565 U30.11@2600,5670 ; U20.11@3295,5670 3295,5555 3285,5545 v1(3305,5545) ; C56.1@3965,5545 3990,5570 U50.11@3990,5670 ; C46.1@4665,5545 4685,5565 U40.11@4685,5670 ; Q160.3@6305,5631.18 6323.82,5650 v1(6335,5650) ; v1(6965,5650) 7005,5690 U120.11@7005,5745 ; v1(7625,5650) 7665,5690 U130.11@7665,5745 ; v1(8285,5650) 8325,5690 U140.11@8325,5745 ; v1(8945,5650) 8985,5690 U150.11@8985,5745
  Bottom Layer w25: C56.1@3965,5545 C56.1@3970,5545 v1(4000,5545) ; C46.1@4665,5545 v1(4695,5545)
  Bottom Layer w45: v1(6335,5650) 6335,5710 R167.1@6370,5745 ; C156.1@8945,5620 v1(8945,5650)
NetC27_2: C27.2 R26.1 R27.1 U20.10 | length 310.4
  Bottom Layer w23: U20.10@3345,5670 3345,5570 C27.2@3370,5545
  Bottom Layer w45: C27.2@3370,5545 R27.1@3455,5545 R26.1@3545,5545
NetC30_1: C30.1 C32.1 R37.2 U30.5 | length 540.4
  Top Layer w45: v2(2565,6290) v2(2720,6290)
  Bottom Layer w23: C32.1@2545,6235 2550,6230 U30.5@2550,6030
  Bottom Layer w45: C32.1@2545,6235 2565,6255 v2(2565,6290) ; v2(2720,6290) R37.2@2720,6330
  Bottom Layer w60: v2(2565,6290) C30.1@2565,6365
NetC31_1: C31.1 C32.2 R34.2 U30.3 | length 349.5
  Bottom Layer w23: U30.3@2450,6030 2450,6135 C31.1@2455,6140
  Bottom Layer w45: R34.2@2325,6265 2355,6235 C32.2@2455,6235 C31.1@2455,6140
NetC31_2: C31.2 R30.2 U30.2 | length 483.7
  Bottom Layer w12: R30.2@2070,6165 2160,6075 2300,6075 C31.2@2365,6140
  Bottom Layer w23: C31.2@2365,6140 2400,6105 U30.2@2400,6030
NetC33_1: C33.1 R38.1 U30.1 U30.8 | length 775.2
  Bottom Layer w23: R38.1@2070,6070 2110,6030 U30.1@2350,6030 2350,5981.5 2376.5,5955 2690,5955 2700,5965 U30.8@2700,6030
NetC34_2: C34.2 C35.2 R35.2 U30.15 | length 305
  Bottom Layer w23: C34.2@2400,5545 U30.15@2400,5670
  Bottom Layer w45: C35.2@2310,5545 C34.2@2400,5545 R35.2@2490,5545
NetC37_2: C37.2 R36.1 R39.1 U30.10 | length 313.3
  Bottom Layer w23: U30.10@2650,5670 2650,5565.76 2670,5545.76 C37.2@2670,5545
  Bottom Layer w45: C37.2@2670,5545 R39.1@2760,5545 R36.1@2850,5545
NetC41_1: C41.1 C42.2 R44.2 U40.3 | length 338.6
  Bottom Layer w23: C42.2@4490,6245 4490,6190 4535,6145 C41.1@4535,6140 U40.3@4535,6030
  Bottom Layer w45: R44.2@4385,6245 C42.2@4490,6245
NetC41_2: C41.2 R40.2 U40.2 | length 685.4
  Bottom Layer w12: R40.2@4285,6405 4245,6365 4245,6100 4270,6075 4380,6075 C41.2@4445,6140
  Bottom Layer w23: C41.2@4445,6140 4485,6100 U40.2@4485,6030
NetC44_2: C44.2 C45.2 R45.2 U40.15 | length 305
  Bottom Layer w23: C44.2@4485,5545 U40.15@4485,5670
  Bottom Layer w45: C45.2@4395,5545 C44.2@4485,5545 R45.2@4575,5545
NetC47_2: C47.2 R46.1 R47.1 U40.10 | length 313.3
  Bottom Layer w23: U40.10@4735,5670 4735,5565 C47.2@4755,5545
  Bottom Layer w45: C47.2@4755,5545 R47.1@4845,5545 R46.1@4935,5545
NetC50_1: C50.1 C52.1 R57.2 U50.5 | length 547.4
  Top Layer w25: v1(3950,6285) v1(4115,6285)
  Bottom Layer w23: C52.1@3930,6235 3940,6225 U50.5@3940,6030
  Bottom Layer w45: C52.1@3930,6235 3950,6255 v1(3950,6285) C50.1@3950,6365 ; v1(4115,6285) R57.2@4115,6320
NetC51_1: C51.1 C52.2 R54.2 U50.3 | length 338.6
  Bottom Layer w23: C51.1@3835,6135 3840,6130 U50.3@3840,6030
  Bottom Layer w45: R54.2@3715,6275 3755,6235 C52.2@3840,6235 ; C51.1@3845,6145 C52.2@3845,6235
NetC51_2: C51.2 R50.2 U50.2 | length 759.9
  Bottom Layer w12: R50.2@3530,6450 3580,6400 3580,6220 3545,6185 3545,6105 3575,6075 3685,6075 3735,6125 3765,6125 C51.2@3750,6140
  Bottom Layer w23: C51.2@3765,6125 3790,6100 U50.2@3790,6030
NetC53_1: C53.1 R58.1 U50.1 U50.8 | length 898.3
  Bottom Layer w23: R58.1@3520,6245 3510,6235 3510,6095 3595,6010 C53.1@3620,6010 3720,6010 U50.1@3740,6030 3740,5975 3760,5955 4060,5955 4090,5985 U50.8@4090,6030
NetC54_2: C54.2 C55.2 R55.2 U50.15 | length 302.1
  Bottom Layer w23: C54.2@3785,5545 3790,5550 U50.15@3790,5670
  Bottom Layer w45: C55.2@3700,5545 3785,5545 C54.2@3790,5545 R55.2@3875,5545
NetC57_2: C57.2 R56.1 R59.1 U50.10 | length 311.2
  Bottom Layer w23: U50.10@4040,5670 4040,5560 C57.2@4055,5545
  Bottom Layer w45: C57.2@4060,5545 R59.1@4150,5545 R56.1@4240,5545
NetC60_1: C60.1 D60.2 R60.1 R61.1 | length 350
  Bottom Layer w60: D60.2@5360,3345 C60.1@5360,3235 R60.1@5485,3235 R61.1@5600,3235
NetC61_2: C61.2 C63.2 D63.2 R65.1 R67.1 U60.2 | length 1171.1
  Bottom Layer w12: C63.2@5425,3925 5450,3900 5715,3900 R67.1@5760,3945 ; 5710,3895 5710,3515 R65.1@5760,3465
  Bottom Layer w25: R65.1@5760,3465 5845,3550 U60.2@5875,3550
  Bottom Layer w45: U60.2@5875,3550 C61.2@5975,3550
  Bottom Layer w60: D63.2@5410,3825 5410,3910 C63.2@5425,3925
NetC62_2: C62.2 R62.1 U60.5 | length 219.5
  Bottom Layer w45: U60.5@5525,3750 5560,3785 C62.2@5560,3855 R62.1@5660,3855
NetC64_2: C64.2 C65.2 U60.4 | length 190
  Bottom Layer w45: U60.4@5875,3750 C65.2@5875,3840 C64.2@5975,3840
NetC65_1: C65.1 R64.1 | length 100
  Bottom Layer w45: C65.1@5875,3930 R64.1@5975,3930
NetC66_2: C66.2 C69.2 R65.2 R66.1 U60.3 | length 405
  Bottom Layer w45: R65.2@5760,3555 5760,3650 U60.3@5875,3650 C66.2@5975,3650 R66.1@5975,3745
NetC69_1: C69.1 R67.2 | length 105
  Bottom Layer w45: C69.1@5760,3750 R67.2@5760,3855
NetC70_2: C70.2 C74.2 D74.2 U70.2 | length 994.9
  Top Layer w12: U70.2@3475,4625 3540,4625 3575,4590 3575,4510 3740,4345 v2(4015,4345)
  Bottom Layer w45: U70.2@3475,4625 3480,4630 C70.2@3575,4630
  Bottom Layer w60: v2(4015,4345) C74.2@4070,4345 D74.2@4070,4480
NetC72_2: C72.2 D70.2 R70.1 R71.2 U70.4 | length 395
  Bottom Layer w45: R71.2@3080,4430 D70.2@3190,4430 R70.1@3280,4430 C72.2@3375,4430 U70.4@3475,4430
NetC73_2: C73.2 R72.1 R106.1 U70.5 | length 917.1
  Bottom Layer w12: R106.1@3225,4660 3140,4575 3140,4490 3155,4475 3530,4475 R72.1@3575,4430
  Bottom Layer w45: R72.1@3575,4430 C73.2@3670,4430 3675,4425 U70.5@3825,4425
NetC75_1: C75.1 D73.2 R74.1 R75.1 | length 362.4
  Bottom Layer w60: R75.1@3985,4825 R74.1@4095,4825 ; D73.2@4125,4695 4125,4795 R74.1@4095,4825 ; C75.1@4205,4825 R74.1@4095,4825
NetC85_1: C85.1 R68.1 R86.2 R87.1 U81.1 | length 492.9
  Bottom Layer w23: C85.1@3435,3905 3516.22,3905 U81.1@3523.82,3912.6 3551.42,3885 3705,3885 R87.1@3725,3905
  Bottom Layer w45: R87.1@3725,3905 R68.1@3815,3905 R86.2@3905,3905
NetC85_2: C85.2 R85.2 | length 90
  Bottom Layer w45: R85.2@3345,3995 C85.2@3435,3995
NetC88_2: C88.2 R88.2 R89.1 U82.8 | length 395.3
  Bottom Layer w23: U82.8@2481.3,3985 2535,3985 2575,4025 C88.2@2575,4100
  Bottom Layer w45: C88.2@2575,4100 R89.1@2685,4100 R88.2@2685,4000
NetC90_2: C90.2 D91.2 U90.2 U92.4 | length 1544.5
  Bottom Layer w12: U90.2@1825,2450 1900,2375 1900,2250 2050,2100 2350,2100 D91.2@2570,2320
  Bottom Layer w15: U90.2@1825,2450 1890,2515 1890,2735 1904,2749 U92.4@1912.5,2749
  Bottom Layer w60: C90.2@1675,2450 U90.2@1825,2450
NetC91_2: C91.2 U91.5 U92.5 | length 245.4
  Bottom Layer w15: C91.2@1837.5,2807.5 1837.5,2801 U92.5@1912.5,2801
  Bottom Layer w23: U91.5@1712.4,2901.18 1793.58,2820 C91.2@1825,2820 C91.2@1837.5,2807.5
NetC92_1: C92.1 R90.2 | length 171.6
  Bottom Layer w45: C92.1@1545,2810 1545,2740 1585,2700 R90.2@1630,2700
NetC92_2: C92.2 R91.1 R95.1 U91.4 | length 527.4
  Bottom Layer w12: R91.1@1545,3030 1590,3075 1760,3075 R95.1@1810,3125
  Bottom Layer w23: C92.2@1545,2900 1546.18,2901.18 U91.4@1637.6,2901.18
  Bottom Layer w45: C92.2@1545,2900 R91.1@1545,3030
NetC111_2: C111.2 D110.1 U110.2 | length 534.7
  Top Layer w23: v1(6045,4500) 6090,4545 v1(6090,4795)
  Bottom Layer w23: v1(6045,4500) 6046,4501 U110.2@6093.7,4501
  Bottom Layer w45: v1(6090,4795) C111.2@6120,4795 6120,4830 6185,4895 D110.1@6200,4895
NetC112_2: C112.2 R110.2 | length 90
  Bottom Layer w45: C112.2@6210,4795 R110.2@6300,4795
NetC113_1: C113.1 D110.2 U110.7 | length 874.6
  Bottom Layer w12: D110.2@6290,4895 6335,4850 6525,4850 6625,4750 6625,4660 6615,4650 6500,4650 6430,4580 C113.1@6430,4575
  Bottom Layer w23: U110.7@6306.3,4501 6351,4501 C113.1@6430,4580
NetC113_2: C113.2 D111.2 L110.1 U110.8 | length 312.9
  Bottom Layer w23: U110.8@6306.3,4451 6416,4451 6430,4465 C113.2@6440,4475
  Bottom Layer w70: D111.2@6430,4395 C113.2@6430,4465 ; C113.2@6440,4475 L110.1@6539.25,4475
NetC115_2: C115.2 FAN1.3 | length 149.5
  Bottom Layer w70: FAN1.3@5650,5175 5750,5175 C115.2@5785,5140
NetC116_2: C116.2 FAN2.3 | length 145
  Bottom Layer w70: FAN2.3@6000,5175 C116.2@6145,5175
NetC121_1: C121.1 C122.2 R124.2 U120.3 | length 320
  Bottom Layer w23: U120.3@6855,6105 C121.1@6855,6220
  Bottom Layer w45: R124.2@6755,6325 C122.2@6860,6325 C121.1@6860,6225
NetC121_2: C121.2 R120.2 U120.2 | length 1260.4
  Bottom Layer w12: R120.2@6250,6890 R120.2@6250,6880 6600,6530 6600,6300 6560,6260 6560,6175 6580,6155 6695,6155 C121.2@6767.5,6227.5
  Bottom Layer w23: C121.2@6767.5,6227.5 C121.2@6770,6225 6805,6190 U120.2@6805,6105
NetC124_2: C124.2 C125.2 R125.2 U120.15 | length 313.3
  Bottom Layer w23: C124.2@6785,5620 6805,5640 U120.15@6805,5745
  Bottom Layer w45: C125.2@6695,5620 C124.2@6785,5620 R125.2@6875,5620
NetC127_2: C127.2 R126.1 R127.1 U120.10 | length 305
  Bottom Layer w23: C127.2@7055,5620 U120.10@7055,5745
  Bottom Layer w45: C127.2@7055,5620 R127.1@7145,5620 R126.1@7235,5620
NetC129_1: C129.1 C229.2 | length 105
  Bottom Layer w45: C229.2@3480,7500 C129.1@3480,7605
NetC130_1: C130.1 C132.1 R137.2 U130.5 | length 939.3
  Top Layer w25: v1(7610,6350) v1(7755,6350)
  Bottom Layer w12: v1(7755,6350) 7755,6195 7800,6150 7800,5995 R137.2@7850,5945
  Bottom Layer w23: C132.1@7609,6320 7615,6314 U130.5@7615,6105
  Bottom Layer w45: C132.1@7609,6320 7609,6444 C130.1@7615,6450
NetC131_1: C131.1 C132.2 R134.2 U130.3 | length 324.4
  Bottom Layer w23: U130.3@7515,6105 C131.1@7515,6225
  Bottom Layer w45: R134.2@7410,6320 C132.2@7519,6320 7519,6226 C131.1@7520,6225
NetC131_2: C131.2 R130.2 U130.2 | length 677.1
  Bottom Layer w12: R130.2@7250,6455 7225,6430 7225,6165 7240,6150 7355,6150 C131.2@7430,6225
  Bottom Layer w23: C131.2@7430,6225 7465,6190 U130.2@7465,6105
NetC133_1: C133.1 R138.1 U130.1 U130.8 | length 764.9
  Bottom Layer w23: C133.1@7295,6085 7315,6105 U130.1@7415,6105 7415,6035 7430,6020 7740,6020 7765,6045 U130.8@7765,6105
  Bottom Layer w45: R138.1@7295,5945 C133.1@7295,6085
NetC134_2: C134.2 C135.2 R135.2 U130.15 | length 313.3
  Bottom Layer w23: C134.2@7445,5620 7465,5640 U130.15@7465,5745
  Bottom Layer w45: C135.2@7355,5620 C134.2@7445,5620 R135.2@7535,5620
NetC137_2: C137.2 R136.1 R139.1 U130.10 | length 305
  Bottom Layer w23: C137.2@7715,5620 U130.10@7715,5745
  Bottom Layer w45: C137.2@7715,5620 R139.1@7805,5620 R136.1@7895,5620
NetC141_1: C141.1 C142.2 R144.2 U140.3 | length 327.1
  Bottom Layer w23: U140.3@8175,6105 8175,6220 C141.1@8180,6225
  Bottom Layer w45: R144.2@8075,6325 C142.2@8180,6325 C141.1@8180,6225
NetC141_2: C141.2 R140.2 U140.2 | length 680.4
  Bottom Layer w12: R140.2@7925,6455 7885,6415 7885,6170 7905,6150 8015,6150 C141.2@8090,6225
  Bottom Layer w23: C141.2@8090,6225 8125,6190 U140.2@8125,6105
NetC144_2: C144.2 C145.2 R145.2 U140.15 | length 313.3
  Bottom Layer w23: C144.2@8105,5620 8125,5640 U140.15@8125,5745
  Bottom Layer w45: C145.2@8015,5620 C144.2@8105,5620 R145.2@8195,5620
NetC147_2: C147.2 R146.1 R147.1 U140.10 | length 305
  Bottom Layer w23: C147.2@8375,5620 U140.10@8375,5745
  Bottom Layer w45: C147.2@8375,5620 R147.1@8465,5620 R146.1@8555,5620
NetC150_1: C150.1 C152.1 R157.2 U150.5 | length 796.5
  Top Layer w23: v1(8935,6295) 9175,6055 v1(9175,5980)
  Bottom Layer w23: U150.5@8935,6105 v1(8935,6295) C152.1@8935,6325 ; C150.1@8935,6445 C150.1@8940,6450
  Bottom Layer w45: C152.1@8935,6325 C150.1@8935,6445 ; R157.2@9175,5945 v1(9175,5980)
NetC151_1: C151.1 C152.2 R154.2 U150.3 | length 327.1
  Bottom Layer w23: U150.3@8835,6105 C151.1@8835,6220
  Bottom Layer w45: R154.2@8735,6325 C152.2@8840,6325 C151.1@8840,6225 C151.1@8835,6220
NetC151_2: C151.2 R150.2 U150.2 | length 696.6
  Bottom Layer w12: R150.2@8600,6455 8540,6395 8540,6165 8555,6150 8675,6150 C151.2@8750,6225
  Bottom Layer w23: C151.2@8750,6225 8785,6190 U150.2@8785,6105
NetC153_1: C153.1 R158.1 U150.1 U150.8 | length 761.9
  Bottom Layer w23: C153.1@8615,6085 8715,6085 U150.1@8735,6105 8735,6045 8760,6020 9065,6020 9085,6040 U150.8@9085,6105
  Bottom Layer w45: R158.1@8615,5945 C153.1@8615,6085
NetC154_2: C154.2 C155.2 R155.2 U150.15 | length 313.3
  Bottom Layer w23: C154.2@8765,5620 8785,5640 U150.15@8785,5745
  Bottom Layer w45: C155.2@8675,5620 C154.2@8765,5620 R155.2@8855,5620
NetC157_2: C157.2 R156.1 R159.1 U150.10 | length 305
  Bottom Layer w23: C157.2@9035,5620 U150.10@9035,5745
  Bottom Layer w45: C157.2@9035,5620 R159.1@9125,5620 R156.1@9215,5620
NetC160_1: C160.1 C161.2 R161.2 R162.1 U160.4 | length 398.7
  Bottom Layer w23: U160.4@6775,2506.3 C161.2@6775,2625
  Bottom Layer w45: R162.1@6775,2715 C161.2@6775,2625 C160.1@6875,2625 ; C160.1@6880,2625 R161.2@6880,2715
NetC160_2: C160.2 R160.2 R161.1 U160.7 U160.9 | length 613.4
  Bottom Layer w23: U160.9@6875,2293.7 6875,2410 6925,2460 U160.7@6925,2506.3 6970,2551.3 C160.2@6970,2625
  Bottom Layer w45: R161.1@6970,2715 C160.2@6970,2625 7025,2570 R160.2@7025,2495
NetC162_2: C162.2 R163.2 R164.1 U160.5 U160.6 | length 588.1
  Bottom Layer w12: U160.6@6875,2506.3 6875,2535 6925,2585 6925,2760 R163.2@6880,2805
  Bottom Layer w23: U160.5@6825,2506.3 U160.6@6875,2506.3
  Bottom Layer w45: R164.1@6775,2900 C162.2@6775,2805 R163.2@6880,2805
NetC163_1: C163.1 Q160.1 R165.1 R166.2 | length 302.1
  Bottom Layer w45: R166.2@6355,5340 C163.1@6355,5435 6355,5516.22 Q160.1@6342.4,5528.82 6343.58,5530 R165.1@6450,5530
NetC164_2: C164.2 R163.1 R169.2 | length 3272.8
  Top Layer w12: v1(7700,1800) v1(7700,2295)
  Bottom Layer w12: R163.1@6970,2805 7015,2760 7015,2645 7145,2515 7305,2515 7525,2295 v1(7700,2295) ; v1(7700,1800) 9045,1800 C164.2@9075,1830
  Bottom Layer w45: C164.2@9075,1830 9060,1830 9005,1885 9005,1970 9075,2040 R169.2@9180,2040
NetC169_2: C169.2 R168.1 R252.1 U160.8 | length 656.4
  Bottom Layer w12: U160.8@6925,2293.7 6925,2390 6985,2450 7215,2450 R252.1@7225,2460
  Bottom Layer w23: C169.2@6895,2175 6925,2205 U160.8@6925,2293.7
  Bottom Layer w45: R168.1@6895,2075 C169.2@6895,2175
NetC170_2: C170.2 R171.2 R172.1 U160.3 | length 450.8
  Bottom Layer w25: C170.2@6545,2445 6555,2435 6700,2435 6725,2460 U160.3@6725,2506.3
  Bottom Layer w45: R172.1@6445,2555 R171.2@6445,2445 C170.2@6545,2445
NetC180_2: C180.2 R183.1 R184.1 R210.2 U180.6 | length 1147
  Bottom Layer w12: 4020,2445 4020,2520 4040,2540 U180.6@4080,2540
  Bottom Layer w23: C180.2@3885,2505 3945,2445 4020,2445 4115,2445 4290,2270 4290,2155 R210.2@4350,2095
  Bottom Layer w45: R183.1@3600,2465 3755,2465 R184.1@3795,2505 C180.2@3885,2505
NetC181_2: C181.2 R190.2 U180.7 U181.1 U181.2 | length 912.5
  Bottom Layer w11.8: 3925,2550 C181.2@3972.5,2502.5 ; C181.2@3975,2505 4030,2560 U180.7@4080,2560
  Bottom Layer w12: 3750,2615 3750,2600 ; U181.1@3866.18,2791.18 3864.29,2789.29 3750,2675 3750,2600 ; 3925,2550 3760,2550 3750,2560 3750,2600
  Bottom Layer w45: U181.1@3862.4,2791.18 3862.5,2791.08 U181.1@3864.29,2789.29 ; U181.1@3866.18,2791.18 U181.2@3937.4,2791.18 3957.4,2791.18 3963.58,2785 R190.2@4105,2785
NetC182_2: C182.2 R189.1 U180.1 | length 209.1
  Bottom Layer w11.8: C182.2@4210,2685 4220,2675 U180.1@4220,2580
  Bottom Layer w45: C182.2@4210,2685 R189.1@4210,2785
NetC183_2: C183.2 R188.1 U180.2 | length 217.4
  Bottom Layer w11.8: U180.2@4220,2560 4300,2560 C183.2@4330,2590
  Bottom Layer w45: C183.2@4330,2590 R188.1@4330,2685
NetC184_2: C184.2 R187.1 U180.4 | length 215.4
  Bottom Layer w11.8: U180.4@4220,2520 4305,2520 C184.2@4330,2495
  Bottom Layer w45: R187.1@4330,2400 C184.2@4330,2495
NetC194_2: "Control Interface.14" C194.2 D194.1 R14.1 R194.1 | length 6707.1
  Top Layer w12: v1(5380,5340) 6040,5340 6175,5205 6175,3000 v1(6200,2975) 6175,2950 6175,2250 6910,1515 v1(6910,1490)
  Top Layer w45: v1(7000,1490) 7050,1440 7050,1300
  Bottom Layer w12: v1(5380,5340) 5380,6445 R14.1@5610,6675
  Bottom Layer w45: v1(6200,2975) D194.1@6265,2975 ; v1(6910,1490) 6925,1490 ; C194.2@6955,1490 v1(7000,1490) R194.1@7050,1490
NetC201_2: C201.2 C212.2 R207.1 U200.16 U201.1 | length 460
  Bottom Layer w12: 5130,2450 R207.1@5340,2450
  Bottom Layer w23: U201.1@5130,2325 C212.2@5130,2405 ; C201.2@5130,2495 U200.16@5130,2575
  Bottom Layer w45: C212.2@5130,2405 5130,2450 C201.2@5130,2495
NetC202_2: C202.2 R202.1 U201.4 | length 231.6
  Bottom Layer w23: U201.4@5130,2175 5215,2175 C202.2@5255,2135
  Bottom Layer w45: R202.1@5255,2045 C202.2@5255,2135
NetC204_2: C204.2 Q200.1 R200.2 | length 202.5
  Bottom Layer w45: R200.2@6145,2375 C204.2@6240,2375 6263.82,2351.18 Q200.1@6337.6,2351.18
NetC205_2: C205.2 R203.2 U200.4 | length 231.6
  Bottom Layer w23: C205.2@4645,2685 4685,2725 U200.4@4770,2725
  Bottom Layer w45: R203.2@4645,2595 C205.2@4645,2685
NetC208_2: C208.2 R208.1 U201.3 | length 215
  Bottom Layer w23: U201.3@5130,2225 C208.2@5255,2225
  Bottom Layer w45: C208.2@5255,2225 R208.1@5255,2315
NetC209_2: "Control Interface.10" C209.2 R205.2 | length 300.7
  Top Layer w12: v1(6800,1490) 6850,1440 6850,1300
  Bottom Layer w45: R205.2@6750,1490 v1(6800,1490) C209.2@6840,1490
NetC210_2: C210.2 R210.1 U211.1 | length 293.7
  Bottom Layer w45: R210.1@4350,2005 4431.22,2005 U211.1@4438.82,2012.6 4461.42,1990 4610,1990 C210.2@4625,2005
NetC214_2: C214.2 R213.1 | length 120
  Bottom Layer w60: C214.2@5100,6965 R213.1@5100,7085
NetC217_2: C217.2 T41-.1 | length 110
  Bottom Layer w45: T41-.1@7215,1855 C217.2@7325,1855
NetC239_2: "Control Interface.3" C239.2 R193.2 | length 3390
  Top Layer w12: 6550,1200 6600,1250 v1(6600,1400)
  Bottom Layer w12: v1(6600,1400) 6600,1510 6760,1670 7660,1670 7740,1750 9190,1750 9290,1850 9370,1850 R193.2@9475,1955
NetC240_2: "Control Interface.4" C240.2 R240.2 | length 3219.3
  Bottom Layer w12: 6550,1300 6550,1400 6575,1425 6575,1520 6750,1695 7650,1695 7730,1775 9120,1775 C240.2@9175,1830 9220,1875 9310,1875 9375,1940 R240.2@9375,1955
NetC260_1: C260.1 C261.2 R260.1 R261.2 | length 370
  Bottom Layer w60: C261.2@7400,2840 R261.2@7525,2840 R260.1@7525,2960 C260.1@7400,2960
NetC261_1: C261.1 R261.1 R262.2 | length 245
  Bottom Layer w60: C261.1@7400,2710 R261.1@7525,2710 R262.2@7525,2590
